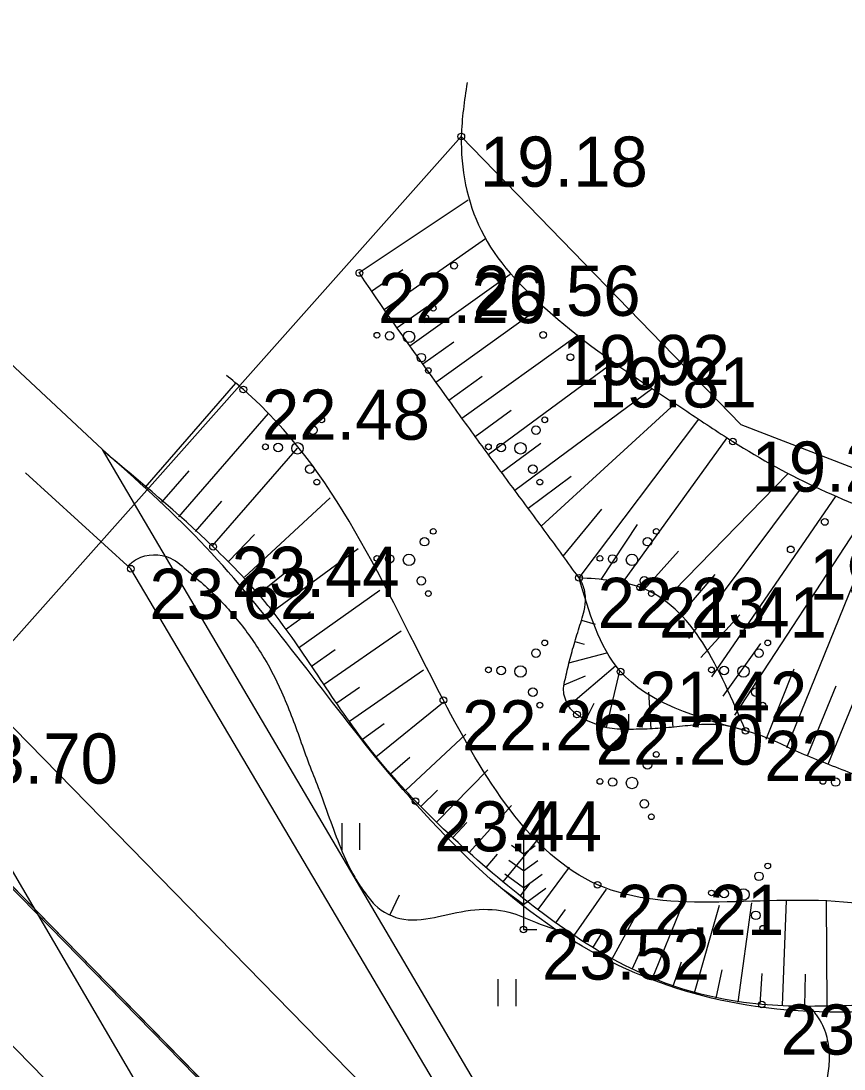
# Model space of a CAD drawing. Extents: x 521824 to 524158, y 294774 to 296228.
# Drawn here: x 522021.3 to 522039.75, y 296028.59 to 296052.08 of the extents above; entities that cross this region are included whole.
import ezdxf

# ---------------------------------------------------------------- set-up
doc = ezdxf.new("R2010")
doc.units = 0
for name, color, linetype in [('7315030100', 7, 'Continuous'), ('CELI_CMAL_####_####_#', 7, 'Continuous'), ('Geolite Projekts', 7, 'Continuous'), ('HIDG_PLIN_####_####_#', 7, 'Continuous'), ('RAMI_UZMR_####_####_#', 7, 'Continuous'), ('RELJ_AATZ_####_TKST_#', 7, 'Continuous'), ('RELJ_ELEM_####_####_#', 7, 'Continuous'), ('RELJ_HORZ_PAMT_####_#', 7, 'Continuous'), ('RELJ_NOGA_####_####_#', 7, 'Continuous'), ('RELJ_NOGL_####_####_#', 7, 'Continuous'), ('ROBZ_IERR_####_####_#', 7, 'Continuous'), ('ROBZ_PROJ_####_####_#', 7, 'Continuous'), ('ROBZ_UZMR_####_####_#', 7, 'Continuous'), ('TERT_DIAM_####_TKST_#', 7, 'Continuous'), ('TERT_ELEM_####_####_#', 7, 'Continuous'), ('TERT_KONT_####_####_#', 7, 'Continuous')]:
    doc.layers.add(name, color=color, linetype=linetype)

msp = doc.modelspace()

# ---------------------------------------------------------------- linework, layer by layer
at = {"layer": '7315030100'}
msp.add_lwpolyline([(521982.6621484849, 296071.9435568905), (522030.78400000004, 296022.73900000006), (522033.5410000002, 296023.5089999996), (522041.3830000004, 296002.9110000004), (522075.3820000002, 295945.0490000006), (522118.8880000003, 295885.8499999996), (522163.66299999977, 295827.4399999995), (522159.46399999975, 295824.69800000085), (522114.8890000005, 295882.8479999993), (522071.2010000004, 295942.2949999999), (522036.86299999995, 296000.73299999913), (522028.99600000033, 296021.0460000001), (521979.24799999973, 296071.9199999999), (521979.2263936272, 296071.94480188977)], dxfattribs=at)
at = {"layer": 'CELI_CMAL_####_####_#'}
for points in [[(522062.798, 295959.285), (522062.798, 295959.285), (522058.043, 295967.908), (522052.45, 295979.914), (522045.71900000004, 295994.345), (522039.629, 296007.129), (522036.52900000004, 296013.324), (522032.55600000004, 296024.949), (522023.76300000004, 296039.8020000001), (522021.40314783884, 296041.95388574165)], [(522016.9257339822, 296038.30610503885), (522019.291, 296036.109), (522026.14400000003, 296024.408), (522024.61100000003, 296016.559), (522016.21, 296007.977), (522009.446, 296002.95800000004), (521998.646, 295996.811), (521986.57700000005, 295992.07800000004), (521974.364, 295987.793), (521962.15, 295983.065), (521949.049, 295978.08900000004), (521936.439, 295973.322), (521922.423, 295968.209), (521916.609, 295966.986)]]:
    msp.add_lwpolyline(points, dxfattribs=at)
at = {"layer": 'Geolite Projekts'}
msp.add_lwpolyline([(522051.64057789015, 295994.0775989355), (522023.12631726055, 296042.47261408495), (521958.08200000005, 296103.28)], dxfattribs=at)
at = {"layer": 'HIDG_PLIN_####_####_#'}
msp.add_spline([(522031.3024014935, 296050.69658941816), (522031.173, 296049.489), (522031.61527393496, 296047.3902310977), (522033.10356148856, 296045.5980747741), (522035.14856829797, 296044.0423810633), (522036.22693693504, 296043.3312858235), (522037.261, 296042.653), (522039.2199077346, 296041.5852114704), (522041.25685016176, 296040.7651794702), (522043.27086750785, 296039.9738077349), (522045.161, 296038.9920000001), (522045.72860179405, 296038.53251211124), (522046.2439666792, 296037.9979730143), (522046.78134822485, 296037.46519741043), (522047.41500000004, 296037.011), (522049.42746192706, 296036.01895480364)], degree=3, dxfattribs=at)
at = {"layer": 'RAMI_UZMR_####_####_#'}
msp.add_lwpolyline([(522023.72900000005, 296021.723), (522015.46800000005, 296031.8340000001), (522031.173, 296049.489), (522037.43799330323, 296043.03493037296), (522045.25731776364, 296040.0155269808), (522064.8556709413, 296037.7736620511), (522081.00594674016, 296041.1695226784), (522170.455, 296046.16700000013), (522192.824, 296044.95), (522215.98600000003, 296046.637), (522238.336, 296053.36), (522285.71800000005, 296059.4810000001)], dxfattribs=at)
at = {"layer": 'RELJ_ELEM_####_####_#'}
for centre in [(522031.173, 296049.489), (522028.88700000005, 296046.43100000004), (522031.01, 296046.595), (522033.01, 296045.042), (522033.618, 296044.5410000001), (522026.286, 296043.819), (522037.261, 296042.653), (522039.321, 296040.8510000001), (522025.607, 296040.296), (522038.558, 296040.235), (522023.76300000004, 296039.8020000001), (522033.81200000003, 296039.599), (522035.18600000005, 296039.384), (522034.74500000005, 296037.495), (522030.771, 296036.85500000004), (522033.76700000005, 296036.533), (522037.54600000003, 296036.169), (522030.147, 296034.591), (522034.22900000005, 296032.718), (522032.56600000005, 296031.717), (522037.913, 296030.036)]:
    msp.add_circle(centre, 0.075, dxfattribs=at)
at = {"layer": 'RELJ_HORZ_PAMT_####_#'}
msp.add_line((522029.77868953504, 296032.4824071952), (522029.5635432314, 296032.0310624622), dxfattribs=at)
for points in [[(522023.6959374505, 296039.86315253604), (522023.8992595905, 296040.0189459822), (522024.6525432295, 296040.04030497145), (522025.05343887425, 296039.73984872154), (522025.4308317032, 296039.416578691), (522026.1107858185, 296038.70493442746), (522026.68375938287, 296037.91204646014), (522027.1411062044, 296037.04458906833), (522027.36058626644, 296036.50892776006), (522027.56074916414, 296035.9705511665), (522027.7575290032, 296035.43200877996), (522027.9668598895, 296034.8958500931), (522028.46907086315, 296033.54163908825), (522028.78331207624, 296032.88731675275), (522028.98723394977, 296032.5726529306), (522029.1047723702, 296032.41929555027), (522029.2341727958, 296032.2689117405), (522029.8868721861, 296031.9451149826), (522030.66483521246, 296032.00624249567), (522031.4791836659, 296032.1572476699), (522032.24103933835, 296032.1030838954), (522032.8365075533, 296031.8798250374), (522033.7097553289, 296031.5769042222)], [(522038.9696438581, 296029.99821267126), (522039.10260162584, 296029.84213894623), (522039.1619235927, 296029.75751682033), (522039.2181031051, 296029.6688450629), (522039.31697111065, 296029.4633469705), (522039.3795318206, 296029.24464273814), (522039.4137779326, 296029.02787579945), (522039.4215102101, 296028.81113468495), (522039.3765568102, 296028.39134513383), (522039.25207010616, 296027.8088900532), (522039.10909953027, 296027.23597247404), (522038.9449373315, 296026.6677590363), (522038.8527945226, 296026.38664001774), (522038.75369883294, 296026.10724427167), (522038.52053053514, 296025.53800473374), (522038.2468411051, 296024.987635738), (522038.0899260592, 296024.711638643), (522037.9255739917, 296024.44188778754), (522037.56375078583, 296023.9240009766), (522037.3620715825, 296023.68516083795), (522037.153514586, 296023.46918646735), (522036.9466143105, 296023.25894292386), (522036.7499052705, 296023.0372952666), (522036.13544973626, 296022.2452210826), (522035.5192878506, 296021.44971727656), (522035.34011985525, 296021.2443432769), (522035.2411920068, 296021.1499948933), (522035.13576210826, 296021.06182030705), (522034.9469641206, 296020.9312470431), (522034.74908745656, 296020.8159216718), (522034.3509145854, 296020.6102004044), (522034.078558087, 296020.4939942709)]]:
    msp.add_spline(points, degree=3, dxfattribs=at)
at = {"layer": 'RELJ_NOGA_####_####_#'}
for p, q in [((522028.8805962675, 296046.44059388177), (522031.3294124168, 296048.07287516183)), ((522029.445137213, 296045.61520572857), (522031.7153574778, 296047.2048348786)), ((522029.16105267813, 296046.0266594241), (522029.86345495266, 296046.506005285)), ((522030.0218850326, 296044.7982894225), (522032.271368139, 296046.4056614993)), ((522029.73238623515, 296045.2059534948), (522030.40573312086, 296045.68074457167)), ((522030.60454874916, 296043.9855767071), (522032.9857966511, 296045.6962640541)), ((522030.31288676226, 296044.3916964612), (522031.00227651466, 296044.88595534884)), ((522031.1878912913, 296043.17335046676), (522033.7906232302, 296045.0422400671)), ((522031.77742385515, 296042.36561615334), (522034.58460703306, 296044.43463706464)), ((522024.0818865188, 296041.62416213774), (522026.1171661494, 296043.9612505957)), ((522030.8962609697, 296043.5794929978), (522031.6433155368, 296044.11591493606)), ((522032.37128763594, 296041.5610507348), (522035.45238708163, 296043.84183708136)), ((522032.9660875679, 296040.75717700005), (522035.96674539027, 296043.5025740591)), ((522024.83600791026, 296040.967427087), (522026.8527869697, 296043.28327154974)), ((522031.48120186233, 296042.7684211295), (522032.29204011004, 296043.358270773)), ((522033.81200000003, 296039.599), (522036.50179549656, 296043.1505821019)), ((522034.8079158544, 296039.5162399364), (522037.13116119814, 296042.737897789)), ((522025.59012930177, 296040.31069203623), (522027.502725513, 296042.50690451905)), ((522032.07421311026, 296041.96322816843), (522032.9558319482, 296042.61424699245)), ((522023.3277651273, 296042.28089718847), (522023.32842186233, 296042.28165130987)), ((522023.704825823, 296041.9525296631), (522023.70502284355, 296041.9527558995)), ((522024.45894721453, 296041.2957946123), (522025.0699900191, 296041.99744811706)), ((522032.66877426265, 296041.15917798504), (522033.6371904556, 296041.87604885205)), ((522035.653930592, 296039.01510416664), (522038.49138167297, 296041.9261637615)), ((522036.27694482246, 296038.2352764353), (522038.7781186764, 296041.58391549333)), ((522026.3090386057, 296039.6163226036), (522028.2344767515, 296041.3939351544)), ((522036.7934520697, 296037.3791894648), (522039.5786206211, 296041.4374176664)), ((522025.21306860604, 296040.6390595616), (522025.8055033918, 296041.3193456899)), ((522033.4599700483, 296040.0846014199), (522034.32397999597, 296041.13459914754)), ((522037.30542762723, 296036.5203174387), (522040.3212533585, 296041.1374731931)), ((522038.47485720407, 296035.7985716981), (522040.59111517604, 296041.0299411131)), ((522034.31020783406, 296039.5599474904), (522035.12070333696, 296040.79272818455)), ((522039.40143422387, 296035.42246712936), (522041.52674599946, 296040.6583945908)), ((522025.9591881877, 296039.9734406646), (522026.53589426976, 296040.57033596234)), ((522026.9393977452, 296038.8408587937), (522028.86162667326, 296040.2547619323)), ((522035.26788848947, 296039.3317238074), (522036.0452683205, 296040.1945266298)), ((522026.63649833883, 296039.23858742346), (522027.21408079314, 296039.71198133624)), ((522033.80524783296, 296039.6083557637), (522033.8060587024, 296039.6089409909)), ((522035.9858174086, 296038.64160727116), (522036.86692453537, 296039.67425748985)), ((522027.52314915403, 296038.0289412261), (522029.34408566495, 296039.31935868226)), ((522033.95713810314, 296039.13996672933), (522033.9654619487, 296039.139955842)), ((522027.23292752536, 296038.436090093), (522027.7949593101, 296038.83979360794)), ((522036.54178574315, 296037.81123007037), (522037.4173438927, 296038.76902976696)), ((522033.8682962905, 296038.65047142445), (522034.1740263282, 296038.5582986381)), ((522028.09850717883, 296037.21104456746), (522029.8237928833, 296038.4081991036)), ((522033.7201680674, 296038.1729193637), (522033.9286959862, 296038.10999293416)), ((522037.04416379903, 296036.94659012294), (522037.8913216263, 296038.12650150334)), ((522027.8116677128, 296037.6205826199), (522028.34181446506, 296037.9944973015)), ((522033.5876522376, 296037.69083059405), (522034.4387454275, 296037.91824765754)), ((522033.5782764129, 296036.7253143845), (522034.6284504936, 296037.6263779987)), ((522028.6674579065, 296036.38867375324), (522030.3242154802, 296037.5376127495)), ((522033.4787199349, 296037.2028968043), (522033.95752485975, 296037.39873989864)), ((522034.4299942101, 296036.2404158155), (522034.72797862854, 296037.5128956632)), ((522038.01082100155, 296035.98476942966), (522038.6378670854, 296037.5571179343)), ((522028.3828641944, 296036.79977731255), (522028.88931431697, 296037.14934908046)), ((522038.93819163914, 296035.6106327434), (522039.57593216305, 296037.17998508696)), ((522035.4269371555, 296036.21382746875), (522035.3812071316, 296037.03888423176)), ((522029.25880469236, 296035.58258055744), (522030.7889248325, 296036.8292458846)), ((522033.9622807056, 296036.413900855), (522034.15492814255, 296036.7869541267)), ((522034.92715640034, 296036.2013983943), (522034.9259044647, 296036.5417859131)), ((522035.9256146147, 296036.2495523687), (522035.9083892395, 296036.41891913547)), ((522036.4231971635, 296036.29858495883), (522036.3989374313, 296036.614361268)), ((522028.95534023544, 296035.9798714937), (522029.44048364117, 296036.32994590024)), ((522036.9226907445, 296036.30375229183), (522036.9254761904, 296036.33954889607)), ((522037.41354851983, 296036.2139337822), (522037.4176110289, 296036.2280493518)), ((522037.54600000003, 296036.169), (522037.54600000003, 296036.1690090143)), ((522029.91875315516, 296034.8315626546), (522031.2718059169, 296036.09347052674)), ((522029.58195777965, 296035.20109110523), (522030.0168802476, 296035.5815727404)), ((522030.61882960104, 296034.11764320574), (522031.76781041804, 296035.29507312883)), ((522030.2642410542, 296034.47013670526), (522030.63960738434, 296034.83941533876)), ((522031.3524028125, 296033.4381361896), (522032.2995018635, 296034.49532583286)), ((522030.9821495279, 296033.7741500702), (522031.2936341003, 296034.11248876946)), ((522032.1080652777, 296032.78323985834), (522032.9062662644, 296033.74488973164)), ((522031.72781239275, 296033.1078894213), (522031.9880123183, 296033.40722720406)), ((522032.8928562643, 296032.16364877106), (522033.600513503, 296033.114585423)), ((522032.49658590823, 296032.4685386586), (522032.7197745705, 296032.7519109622)), ((522033.7049852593, 296031.5802848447), (522034.42598085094, 296032.6225234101)), ((522033.29599271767, 296031.8678918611), (522033.5074410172, 296032.1611867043)), ((522034.5552611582, 296031.0548719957), (522035.2652529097, 296032.3549159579)), ((522035.45800462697, 296030.62586582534), (522036.12583533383, 296032.25563522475)), ((522036.40170199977, 296030.2965951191), (522036.9604569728, 296032.2637693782)), ((522037.37871482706, 296030.0873284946), (522037.68347886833, 296032.3106555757)), ((522038.37559384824, 296030.01465675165), (522038.46542363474, 296032.362084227)), ((522039.3753406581, 296029.9970931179), (522039.3598330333, 296032.3678430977)), ((522034.12304406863, 296031.3061164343), (522034.3399970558, 296031.6531261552)), ((522035.0007452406, 296030.82798456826), (522035.2069611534, 296031.2661234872)), ((522035.92532956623, 296030.448240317), (522036.1128909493, 296030.9889518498)), ((522036.8865356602, 296030.1747706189), (522037.0202134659, 296030.8080614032)), ((522037.87615063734, 296030.0381328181), (522037.9160181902, 296030.72693693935)), ((522038.8753641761, 296029.9998130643), (522038.89001498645, 296030.7126655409))]:
    msp.add_line(p, q, dxfattribs=at)
for points in [[(522033.80524783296, 296039.6083557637), (522033.0771967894, 296040.6069257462), (522032.33362439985, 296041.6119297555), (522031.59101933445, 296042.6185240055), (522030.8591180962, 296043.63122047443), (522028.88700000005, 296046.43100000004), (522028.8805962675, 296046.44059388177)], [(522048.36729814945, 296030.0992004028), (522047.4382755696, 296030.1539824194), (522045.49600000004, 296030.22500000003), (522044.5481421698, 296030.2181364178), (522041.7045081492, 296030.0851765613), (522039.808740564, 296030.0074397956), (522037.913, 296030.036), (522035.7462344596, 296030.51300926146), (522033.73786981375, 296031.5575361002), (522031.87557026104, 296032.980044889), (522030.147, 296034.591), (522028.9365410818, 296036.00592391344), (522027.88978342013, 296037.5098279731), (522026.8366340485, 296038.9805680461), (522025.607, 296040.296), (522023.14334187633, 296042.44150423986)], [(522037.54599999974, 296036.169), (522037.3210256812, 296036.23949394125), (522037.2055528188, 296036.2651439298), (522037.0888476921, 296036.28594360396), (522036.8536789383, 296036.3078242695), (522036.61883208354, 296036.30938031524), (522036.3742938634, 296036.29442397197), (522036.12971908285, 296036.2705543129), (522035.8850685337, 296036.24542864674), (522035.64030300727, 296036.22670428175), (522035.3979808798, 296036.2122225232), (522035.1552557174, 296036.20356447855), (522034.91244655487, 296036.2013442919), (522034.6698724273, 296036.20617610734), (522034.4356298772, 296036.23909607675), (522034.20627521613, 296036.3083437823), (522033.98313283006, 296036.40313266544), (522033.87413215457, 296036.46340300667), (522033.76700000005, 296036.533), (522033.62332211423, 296036.6640415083), (522033.5307468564, 296036.8149667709), (522033.49854548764, 296036.9025482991), (522033.4753202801, 296036.9907897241), (522033.4718437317, 296037.16634916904), (522033.51407669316, 296037.3743326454), (522033.5611941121, 296037.5823894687), (522033.6130763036, 296037.7899402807), (522033.66960358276, 296037.9964057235), (522033.73250555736, 296038.2138037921), (522033.7999368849, 296038.4295515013), (522033.8666285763, 296038.64493974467), (522033.92731164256, 296038.8612594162), (522033.9571495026, 296039.1486820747), (522033.93969440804, 296039.2941905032), (522033.89947644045, 296039.4353361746), (522033.8120000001, 296039.599), (522033.80524783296, 296039.6083557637)], [(522037.54600000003, 296036.169), (522035.18600000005, 296039.384), (522033.81200000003, 296039.599)], [(522048.36756628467, 296030.0987555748), (522047.324, 296031.83), (522047.1669111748, 296032.0198479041), (522046.96704224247, 296032.1720355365), (522046.7450655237, 296032.3015943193), (522046.52165333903, 296032.42355567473), (522046.0315757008, 296032.6985041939), (522045.5402558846, 296032.9658452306), (522045.0415525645, 296033.2152227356), (522044.52932441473, 296033.4362806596), (522043.9024038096, 296033.6740325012), (522043.27383055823, 296033.90709244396), (522042.6454231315, 296034.1404263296), (522042.01900000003, 296034.379), (522040.89771892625, 296034.81795858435), (522039.7800103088, 296035.2687995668), (522038.66354653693, 296035.72224076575), (522037.54600000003, 296036.169), (522037.54599999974, 296036.169)]]:
    msp.add_spline(points, degree=3, dxfattribs=at)
at = {"layer": 'RELJ_NOGL_####_####_#'}
for points in [[(522047.324, 296031.83), (522044.51200000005, 296031.444), (522039.922, 296032.313), (522034.22900000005, 296032.718), (522030.771, 296036.85500000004), (522026.286, 296043.819), (522025.909157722, 296044.1365076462)], [(522037.5459999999, 296036.16900000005), (522034.7269744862, 296037.5139082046), (522033.8120000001, 296039.599)]]:
    msp.add_spline(points, degree=3, dxfattribs=at)
at = {"layer": 'ROBZ_IERR_####_####_#'}
msp.add_lwpolyline([(521982.72142177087, 296071.9435568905), (522030.7829999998, 296022.79399999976), (522033.55399999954, 296023.53500000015), (522231.7470000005, 296043.14800000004), (522293.95000000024, 296059.25), (522300.4160000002, 296060.9240000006), (522337.1440000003, 296010.44299999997), (522362.11199999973, 295976.4340000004), (522359.108, 295971.28500000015), (522349.7560000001, 295955.2589999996), (522172.84800000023, 295833.3920000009), (522168.0970000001, 295830.30399999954), (522159.466, 295824.6950000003), (522157.57199999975, 295823.4639999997), (522100.0300000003, 295786.06900000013), (522037.6330000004, 295748.40699999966), (521945.6600000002, 295684.5130000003), (521914.93752583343, 295661.4435568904)], dxfattribs=at)
at = {"layer": 'ROBZ_PROJ_####_####_#'}
msp.add_lwpolyline([(521986.21768110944, 296071.9435568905), (522033.55399999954, 296023.53500000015), (522030.7829999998, 296022.79399999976), (521982.721421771, 296071.9435568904)], dxfattribs=at)
at = {"layer": 'ROBZ_UZMR_####_####_#'}
msp.add_lwpolyline([(522148.9079999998, 296111.2679999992), (522231.7470000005, 296043.14800000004), (522033.55399999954, 296023.53500000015), (521986.21768110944, 296071.9435568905)], dxfattribs=at)
at = {"layer": 'TERT_ELEM_####_####_#'}
for p, q in [((522028.5, 296033.5), (522028.5, 296034.10000000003)), ((522028.9, 296033.5), (522028.9, 296034.10000000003)), ((522032.56600000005, 296033.967), (522032.56600000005, 296031.717)), ((522032.56600000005, 296033.403), (522032.302, 296033.59500000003)), ((522032.56600000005, 296033.403), (522032.82700000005, 296033.59500000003)), ((522032.56600000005, 296033.028), (522032.242, 296033.265)), ((522032.56600000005, 296033.028), (522032.89, 296033.265)), ((522032.56600000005, 296032.653), (522032.14900000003, 296032.95900000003)), ((522032.56600000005, 296032.653), (522032.983, 296032.95900000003)), ((522032.56600000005, 296032.278), (522032.068, 296032.64400000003)), ((522032.56600000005, 296032.278), (522033.06700000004, 296032.64400000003)), ((522032.56600000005, 296031.717), (522032.86600000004, 296031.717)), ((522032, 296030), (522032, 296030.60000000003)), ((522032.4, 296030), (522032.4, 296030.60000000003))]:
    msp.add_line(p, q, dxfattribs=at)
for centre, radius in [((522030.54400000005, 296045.63936), 0.06400000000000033), ((522030.34752, 296045.40767999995), 0.09600000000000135), ((522029.28160000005, 296045.03423999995), 0.06400000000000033), ((522029.56608, 296045.02079999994), 0.09600000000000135), ((522030, 296045), 0.12800000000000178), ((522030.27647999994, 296044.5331199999), 0.09600000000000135), ((522030.43392, 296044.24383999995), 0.06400000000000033), ((522028.04400000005, 296043.13936), 0.06400000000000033), ((522033.04400000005, 296043.13936), 0.06400000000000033), ((522027.84752, 296042.90767999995), 0.09600000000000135), ((522032.84752, 296042.90767999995), 0.09600000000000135), ((522026.78160000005, 296042.53423999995), 0.06400000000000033), ((522027.06608, 296042.52079999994), 0.09600000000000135), ((522027.5, 296042.5), 0.12800000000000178), ((522031.78160000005, 296042.53423999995), 0.06400000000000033), ((522032.06608, 296042.52079999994), 0.09600000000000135), ((522032.5, 296042.5), 0.12800000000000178), ((522027.77647999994, 296042.0331199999), 0.09600000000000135), ((522032.77647999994, 296042.0331199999), 0.09600000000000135), ((522027.93392, 296041.74383999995), 0.06400000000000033), ((522032.93392, 296041.74383999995), 0.06400000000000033), ((522030.54400000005, 296040.63936), 0.06400000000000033), ((522035.54400000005, 296040.63936), 0.06400000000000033), ((522030.34752, 296040.40767999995), 0.09600000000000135), ((522035.34752, 296040.40767999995), 0.09600000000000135), ((522029.28160000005, 296040.03423999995), 0.06400000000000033), ((522029.56608, 296040.02079999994), 0.09600000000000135), ((522030, 296040), 0.12800000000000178), ((522034.28160000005, 296040.03423999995), 0.06400000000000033), ((522034.56608, 296040.02079999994), 0.09600000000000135), ((522035, 296040), 0.12800000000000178), ((522030.27647999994, 296039.5331199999), 0.09600000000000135), ((522035.27647999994, 296039.5331199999), 0.09600000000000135), ((522030.43392, 296039.24383999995), 0.06400000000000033), ((522035.43392, 296039.24383999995), 0.06400000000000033), ((522033.04400000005, 296038.13936), 0.06400000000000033), ((522038.04400000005, 296038.13936), 0.06400000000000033), ((522032.84752, 296037.90767999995), 0.09600000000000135), ((522037.84752, 296037.90767999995), 0.09600000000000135), ((522031.78160000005, 296037.53423999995), 0.06400000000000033), ((522032.06608, 296037.52079999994), 0.09600000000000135), ((522032.5, 296037.5), 0.12800000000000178), ((522036.78160000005, 296037.53423999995), 0.06400000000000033), ((522037.06608, 296037.52079999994), 0.09600000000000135), ((522037.5, 296037.5), 0.12800000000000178), ((522032.77647999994, 296037.0331199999), 0.09600000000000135), ((522037.77647999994, 296037.0331199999), 0.09600000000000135), ((522032.93392, 296036.74383999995), 0.06400000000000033), ((522037.93392, 296036.74383999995), 0.06400000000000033), ((522035.54400000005, 296035.63936), 0.06400000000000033), ((522035.34752, 296035.40767999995), 0.09600000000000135), ((522034.28160000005, 296035.03423999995), 0.06400000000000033), ((522034.56608, 296035.02079999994), 0.09600000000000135), ((522035, 296035), 0.12800000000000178), ((522039.28160000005, 296035.03423999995), 0.06400000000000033), ((522039.56608, 296035.02079999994), 0.09600000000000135), ((522035.27647999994, 296034.5331199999), 0.09600000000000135), ((522035.43392, 296034.24383999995), 0.06400000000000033), ((522038.04400000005, 296033.13936), 0.06400000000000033), ((522037.84752, 296032.90767999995), 0.09600000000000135), ((522036.78160000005, 296032.53423999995), 0.06400000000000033), ((522037.06608, 296032.52079999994), 0.09600000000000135), ((522037.5, 296032.5), 0.12800000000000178), ((522037.77647999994, 296032.0331199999), 0.09600000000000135), ((522037.93392, 296031.74383999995), 0.06400000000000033)]:
    msp.add_circle(centre, radius, dxfattribs=at)
at = {"layer": 'TERT_KONT_####_####_#'}
msp.add_spline([(522170.455, 296046.167), (522166.971340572, 296040.03181256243), (522160.901513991, 296038.7556647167), (522150.9608099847, 296037.90971206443), (522139.12419851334, 296038.9863790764), (522130.18268898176, 296038.9863790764), (522119.6415349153, 296036.95197828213), (522107.6012645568, 296034.8932966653), (522099.4638639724, 296033.9875679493), (522089.54878033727, 296035.37185410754), (522071.9219649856, 296033.7055837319), (522053.16785330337, 296029.9372491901), (522045.45612158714, 296030.2448683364), (522037.7700102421, 296029.98851904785), (522034.6955657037, 296030.9113764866), (522029.110324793, 296035.7563780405), (522025.3185098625, 296040.42193509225), (522023.12631726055, 296042.47261408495)], degree=3, dxfattribs=at)

# ---------------------------------------------------------------- texts
at = {"layer": 'RELJ_AATZ_####_TKST_#'}
for s, p in [(' 19.18', (522031.173, 296048.364)), (' 20.56', (522031.01, 296045.47)), (' 22.26', (522028.88700000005, 296045.30600000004)), (' 19.92', (522033.01, 296043.917)), (' 19.81', (522033.618, 296043.4160000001)), (' 22.48', (522026.286, 296042.694)), (' 19.23', (522037.261, 296041.528)), (' 23.44', (522025.607, 296039.171)), (' 19.93', (522038.558, 296039.11)), (' 23.62', (522023.76300000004, 296038.6770000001)), (' 22.23', (522033.81200000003, 296038.474)), (' 21.41', (522035.18600000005, 296038.259)), (' 21.42', (522034.74500000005, 296036.37)), (' 22.26', (522030.771, 296035.73000000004)), (' 22.20', (522033.76700000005, 296035.408)), (' 22.19', (522037.54600000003, 296035.044)), (' 23.70', (522019.291, 296034.984)), (' 23.44', (522030.147, 296033.466)), (' 22.21', (522034.22900000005, 296031.593)), (' 23.52', (522032.56600000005, 296030.592)), (' 23.60', (522037.913, 296028.911))]:
    msp.add_text(s, height=1.125, dxfattribs=at).set_placement(p)
at = {"layer": 'TERT_DIAM_####_TKST_#'}
msp.add_text('4', height=1.125, dxfattribs=at).set_placement((522032.3883912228, 296033.4706535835))

doc.saveas('drawing.dxf')
